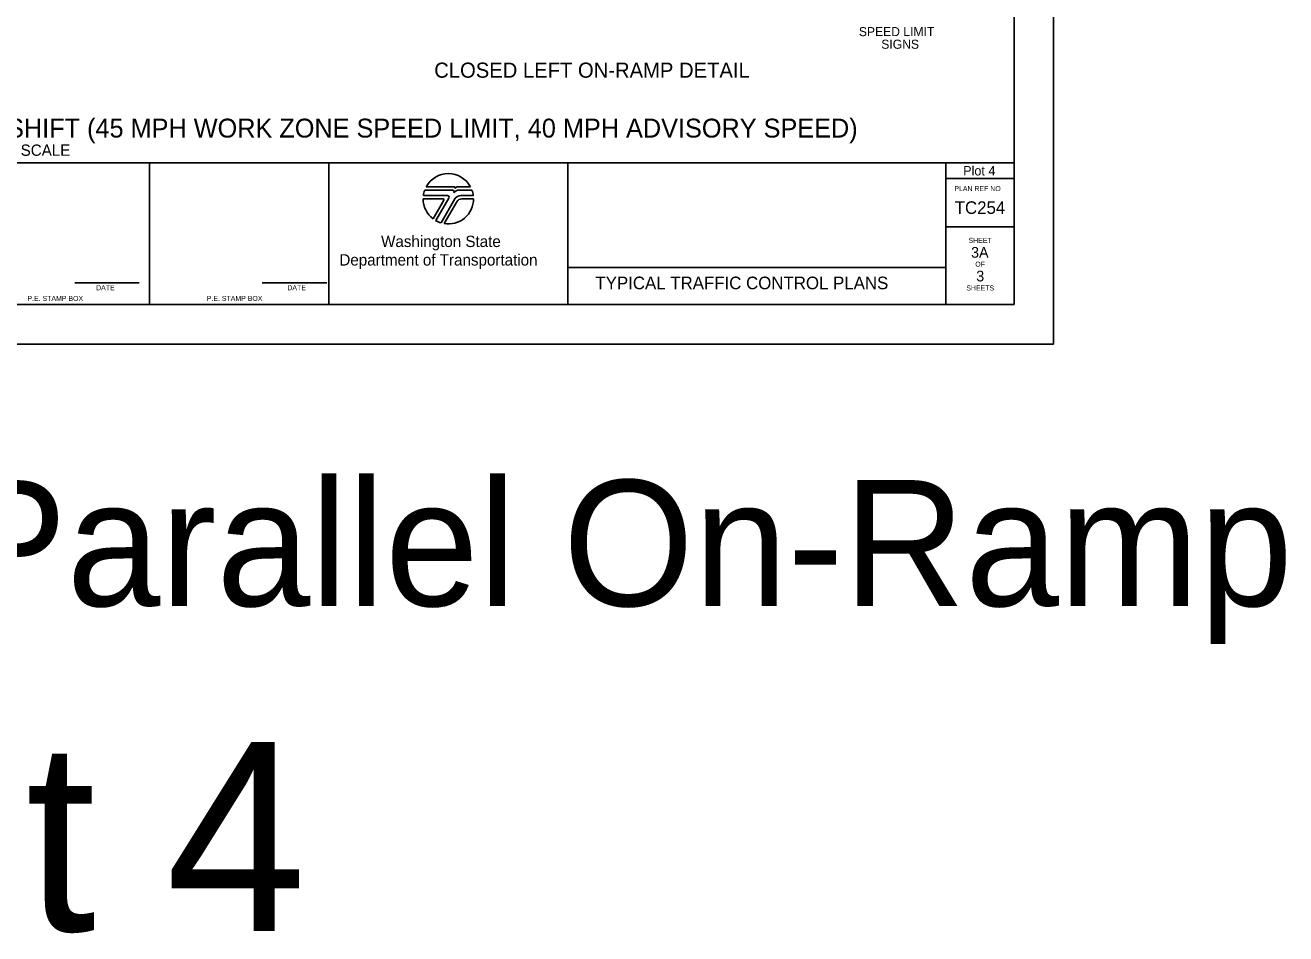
# Model space of a CAD drawing. Extents: x 99999 to 100116, y 99995 to 100013.
# Drawn here: x 100067.9 to 100077.91, y 99995.01 to 100002.22 of the extents above; entities that cross this region are included whole.
import ezdxf

# ---------------------------------------------------------------- set-up
doc = ezdxf.new("R2010")
doc.units = 0
for name, color, linetype in [('SH_DE_DetailHeading1Text', 7, 'Continuous'), ('SH_DE_DetailHeading2Text', 7, 'Continuous'), ('SH_GI_PlotLimits', 7, 'Continuous'), ('SH_GI_SheetBorder', 7, 'Continuous'), ('SH_GI_SheetLocationText', 7, 'Continuous'), ('SH_GI_SheetTextInCells', 7, 'Continuous'), ('SH_GI_TitleBlockText', 7, 'Continuous'), ('SH_GI_WSDOTLogo', 7, 'Continuous'), ('TR_SN_ConstructionSigns', 7, 'Continuous')]:
    doc.layers.add(name, color=color, linetype=linetype)

msp = doc.modelspace()

# ---------------------------------------------------------------- linework, layer by layer
at = {"layer": 'SH_GI_PlotLimits'}
msp.add_lwpolyline([(100059.062, 99999.687), (100076.062, 99999.687), (100076.062, 100010.687), (100059.062, 100010.687)], close=True, dxfattribs=at)
at = {"layer": 'SH_GI_SheetBorder'}
for p, q in [((100075.75, 100010.375), (100075.75, 100000)), ((100060, 100001.126), (100075.75, 100001.126)), ((100068.883, 100000), (100068.883, 100001.126)), ((100070.309, 100001.126), (100070.309, 100000)), ((100072.205, 100001.126), (100072.205, 100000)), ((100075.208, 100001.126), (100075.208, 100000)), ((100075.208, 100001.001), (100075.75, 100001.001)), ((100075.208, 100000.618), (100075.75, 100000.618)), ((100072.205, 100000.295), (100075.208, 100000.295)), ((100068.29, 100000.173), (100068.802, 100000.173)), ((100069.78, 100000.173), (100070.291, 100000.173)), ((100060, 100000), (100075.75, 100000))]:
    msp.add_line(p, q, dxfattribs=at)
at = {"layer": 'SH_GI_WSDOTLogo'}
for p, q in [((100071.289, 100000.909), (100071.07, 100000.909)), ((100071.303, 100000.935), (100071.081, 100000.935)), ((100071.433, 100000.935), (100071.335, 100000.935)), ((100071.445, 100000.909), (100071.343, 100000.909)), ((100071.343, 100000.909), (100071.343, 100000.909)), ((100071.057, 100000.84), (100071.215, 100000.84)), ((100071.059, 100000.866), (100071.25, 100000.866)), ((100071.222, 100000.828), (100071.136, 100000.681)), ((100071.261, 100000.846), (100071.157, 100000.667)), ((100071.199, 100000.649), (100071.309, 100000.839)), ((100071.224, 100000.643), (100071.324, 100000.816)), ((100071.356, 100000.866), (100071.456, 100000.866)), ((100071.365, 100000.839), (100071.457, 100000.839))]:
    msp.add_line(p, q, dxfattribs=at)
for centre, radius, start, end in [((100071.257, 100000.84), 0.2, 28.4787, 151.532), ((100071.257, 100000.84), 0.2, 159.696, 172.5057), ((100071.289, 100000.895), 0.0148, 327.8418, 89.9985), ((100071.343, 100000.861), 0.0484, 89.9953, 147.8238), ((100071.303, 100000.926), 0.00903, 329.8742, 90.0033), ((100071.335, 100000.907), 0.0287, 90.0072, 148.1676), ((100071.257, 100000.84), 0.2, 7.4943, 20.2941), ((100071.257, 100000.84), 0.2, 179.9986, 232.8433), ((100071.215, 100000.832), 0.0082, 329.7436, 90), ((100071.257, 100000.84), 0.2, 260.5455, 359.8086), ((100071.25, 100000.853), 0.0131, 329.7683, 90), ((100071.356, 100000.812), 0.0542, 90, 149.9974), ((100071.365, 100000.792), 0.0476, 90, 150.0543), ((100071.257, 100000.84), 0.2, 239.7929, 253.0448)]:
    msp.add_arc(centre, radius, start, end, dxfattribs=at)

# ---------------------------------------------------------------- texts
at = {"layer": 'SH_DE_DetailHeading1Text'}
for s, height, p in [("FREEWAY (2 LANES): SINGLE LEFT LANE CLOSURE, 9' MAX RIGHT SHOULDER SHIFT (45 MPH WORK ZONE SPEED LIMIT, 40 MPH ADVISORY SPEED)", 0.15, (100060.091, 100001.326)), ('NOT TO SCALE', 0.09, (100067.373, 100001.181))]:
    msp.add_text(s, height=height, rotation=360, dxfattribs=at).set_placement(p)
at = {"layer": 'SH_DE_DetailHeading2Text'}
msp.add_text('CLOSED LEFT ON-RAMP DETAIL', height=0.12, rotation=360, dxfattribs=at).set_placement((100071.145, 100001.801))
at = {"layer": 'SH_GI_SheetBorder'}
msp.add_text('PLAN REF NO', height=0.04003, dxfattribs=at).set_placement((100075.275, 100000.901))
at = {"layer": 'SH_GI_SheetLocationText'}
for s, height, p in [('Plot 4', 0.075, (100075.345, 100001.025)), ('Left Ramps: Parallel On-Ramp', 1, (100059.755, 99997.607)), ('Plot 4', 1.5, (100065.001, 99995.027))]:
    msp.add_text(s, height=height, dxfattribs=at).set_placement(p)
at = {"layer": 'SH_GI_SheetTextInCells'}
for s, height, p in [('Washington State', 0.09007, (100070.723, 100000.457)), ('SHEET', 0.04, (100075.388, 100000.49)), ('Department of Transportation', 0.09007, (100070.392, 100000.31)), ('OF', 0.04, (100075.441, 100000.301)), ('DATE', 0.04, (100068.46, 100000.114)), ('DATE', 0.04, (100069.979, 100000.114)), ('SHEETS', 0.04, (100075.37, 100000.112)), ('P.E. STAMP BOX', 0.04003, (100067.915, 100000.029)), ('P.E. STAMP BOX', 0.04003, (100069.339, 100000.029))]:
    msp.add_text(s, height=height, dxfattribs=at).set_placement(p)
at = {"layer": 'SH_GI_TitleBlockText'}
for s, height, p in [('TC254', 0.1, (100075.278, 100000.72)), ('3A', 0.085, (100075.408, 100000.372)), ('TYPICAL TRAFFIC CONTROL PLANS', 0.1, (100072.425, 100000.122)), ('3', 0.085, (100075.449, 100000.184))]:
    msp.add_text(s, height=height, dxfattribs=at).set_placement(p)
at = {"layer": 'TR_SN_ConstructionSigns'}
for s, p in [('SPEED LIMIT', (100074.517, 100002.131)), ('SIGNS', (100074.695, 100002.031))]:
    msp.add_text(s, height=0.072, dxfattribs=at).set_placement(p)

doc.saveas('drawing.dxf')
